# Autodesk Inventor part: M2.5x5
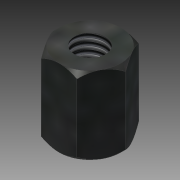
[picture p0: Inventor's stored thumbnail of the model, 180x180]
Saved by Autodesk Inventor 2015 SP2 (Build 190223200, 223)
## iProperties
Created: 2012-08
Part Number: M2.5x5
Material: Stahl
Document SubType Name: Modeling
Designer: rYan
Density: 7.85 g/cm^3
Mass: 3.36246 g
Surface Area: 5.74911 cm^2
Volume: 0.428339 cm^3
Appearance: Platte
Author: rYan
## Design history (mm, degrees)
sketch "Skizze1"
  geometry: L1 (2.309, 0)-(1.155, -2); L2 (1.155, -2)-(-1.155, -2); L3 (-1.155, -2)-(-2.309, 0); L4 (-2.309, 0)-(-1.155, 2); L5 (-1.155, 2)-(1.155, 2); L6 (1.155, 2)-(2.309, 0); 2 further points
  constraints: 12 end point, 1 coincident, 13 other
  dimensions: "SW" = 4 distance between parallel lines of L2 L5
extrude "Extrusion1" new body sketch "Skizze1" taper "d2" = 0 deg; stored distance "L" = 5
sketch "Skizze2"
  geometry: 2 further points
  constraints: 1 coincident
hole "Bohrung1" sketch "Skizze2" at (0, 0) diameter "d3" = 2.013; stored, may be unused: countersink angle "d7" = 90 deg, drill point angle "d9" = 118 deg; dims "d4" = 6, "d5" = 4, "d6" = 2, "d8" = 8
sketch "Innenradius"
  geometry: L1 (2.309, 0)-(1.155, 2) reference; C1 r 2 at (0, 0); 1 further point
  constraints: 1 centre point, 1 coincident, 1 tangent
sketch "Skizze7"
  geometry: L1 (-1.006, 2.5)-(1.006, 2.5) reference; L2 (-1.155, 2.5)-(-2.309, 2.5) reference; L3 (-2.309, 2.5)-(-1.155, 2.5) reference; L4 (-1.155, 2.5)-(1.155, 2.5) reference; L5 (1.155, 2.5)-(2.309, 2.5) reference; L6 (2.309, 2.5)-(1.155, 2.5) reference; L7 (1.155, 2.5)-(-1.155, 2.5) reference; L8 (1.006, -2.5)-(-1.006, -2.5) reference; L9 (-2.309, -2.5)-(-1.155, -2.5) reference; L10 (-1.155, -2.5)-(1.155, -2.5) reference; L11 (1.155, -2.5)-(2.309, -2.5) reference; L12 (2.309, -2.5)-(1.155, -2.5) reference; L13 (1.155, -2.5)-(-1.155, -2.5) reference; L14 (-1.155, -2.5)-(-2.309, -2.5) reference; L15 (0, -45.5)-(0, 45.5) reference; L16 (0, 2.5)-(0, -2.5); L17 (2, 2.5)-(-2, 2.5) reference; L18 (2, 2.5)-(2.309, 2.5); L19 (2.309, 2.191)-(2, 2.5); L20 (2.309, 2.5)-(2.309, 2.191); 1 further point
  constraints: 8 end point, 2 midpoint, 2 point on line, 1 collinear, 1 perpendicular
  dimensions: "d16" = 45 deg angle of L5 L19
revolve "Umdrehung1" sketch "Skizze7" stored, may be unused: angle "d17" = 90 deg
mirror "Spiegeln1"
node "Volumenkörper1"
node "Projizierte Kontur5"
node "Projizierte Kontur6"
